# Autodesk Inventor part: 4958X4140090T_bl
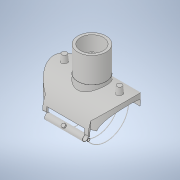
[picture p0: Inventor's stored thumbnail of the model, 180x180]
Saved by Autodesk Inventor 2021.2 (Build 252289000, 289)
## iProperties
Created: 2020-06
Part Number: 4958X4140090T_bl
Material: Generic
Description: Plasson Branch Saddle 140x90
Document SubType Name: Modeling
Designer: KIM
Density: 1 g/cm^3
Appearance: Default
Author: KIM
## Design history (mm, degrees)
derived "4958X4.ipt"
feature "Solid1::4958X4.ipt" dims "ScaleForDerivedMember" = 10
tag "TaggingFeature1"
body "Solid1"
other parameters: "d0" = 242 [user parameter], "d3" = 169.4 [user parameter], "d4" = 106 [user parameter], "d7" = 73 [user parameter], "d9" = 81 [user parameter], "d10" = 0.5 [user parameter], "d11" = 1 [user parameter], "d12" = 26.5 [user parameter], "d13" = 16 [user parameter], "d14" = 8 [user parameter], "d16" = 10 deg [user parameter], "d17" = 10 deg [user parameter], "d19" = 0 [user parameter], "d23" = 0 [user parameter], "d26" = 0 [user parameter], "d27" = 145.2 [user parameter], "d28" = 0 [user parameter], "d29" = 121 [user parameter], "d30" = 0 [user parameter], "d31" = 1 [user parameter], "d32" = 1 [user parameter], "d33" = 19.2 [user parameter], "d34" = 9.6 [user parameter], "d35" = 45 deg [user parameter], "d36" = 121 [user parameter], "d37" = 0 [user parameter], "d38" = 5 [user parameter], "d39" = 85 deg [user parameter], "d40" = 26.5 [user parameter], "d41" = 16 [user parameter], "d42" = 88 [user parameter], "d49" = 3 [user parameter], "d50" = 6 [user parameter], "d51" = 5 [user parameter], "d54" = 0 [user parameter], "d57" = 35 deg [user parameter], "d60" = 15.125 [user parameter], "d61" = 1 [user parameter], "d62" = 90 deg [user parameter], "d63" = 2 [user parameter], "d64" = 0 [user parameter], "d65" = 0 [user parameter], "d68" = 30.25 [user parameter], "d70" = 0.57711 [user parameter], "d71" = 10 deg [user parameter], "d73" = 5.145 [user parameter], "B" = 189 [user parameter], "L" = 242 [user parameter], "LS" = 81 [user parameter], "H1" = 106 [user parameter], "Dt" = 16 [user parameter], "di" = 73 [user parameter], "d72" = 14.7 [user parameter]
